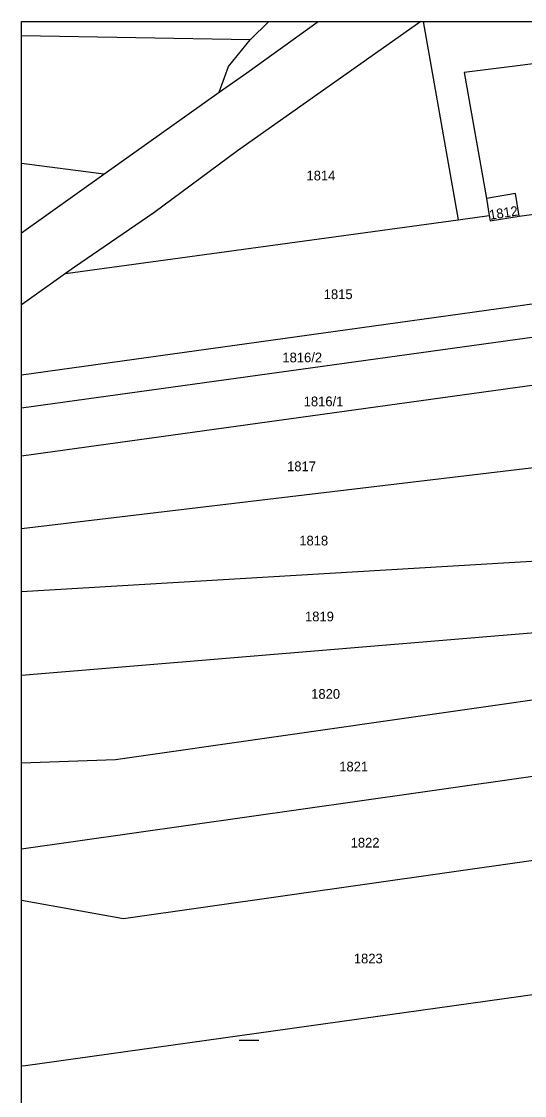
# Model space of a CAD drawing. Extents: x -601800 to -601487, y -1201912 to -1200862.
# Drawn here: x -601783.7 to -601680, y -1201083.7 to -1200862.4 of the extents above; entities that cross this region are included whole.
import ezdxf

# ---------------------------------------------------------------- set-up
doc = ezdxf.new("R2010")
doc.units = 0
for name, color, linetype in [('Hranice parcel', 7, 'Continuous'), ('Parcelní čísla', 7, 'Continuous'), ('x_rám', 7, 'Continuous')]:
    doc.layers.add(name, color=color, linetype=linetype)

msp = doc.modelspace()

# ---------------------------------------------------------------- linework, layer by layer
at = {"layer": 'Hranice parcel'}
for p, q in [((-601700.91, -1200862.35), (-601693.73, -1200903.21)), ((-601766.68, -1200893.84), (-601742.92, -1200876.94)), ((-601766.68, -1200893.84), (-601783.66, -1200891.65)), ((-601681.14, -1200902.44), (-601637.83, -1200896.61)), ((-601687.91, -1200898.84), (-601687.31, -1200902.33)), ((-601774.62, -1200914.32), (-601693.73, -1200903.21)), ((-601693.73, -1200903.21), (-601687.31, -1200902.33)), ((-601783.66, -1200935.2), (-601635.81, -1200914.55)), ((-601634.83, -1200921.38), (-601783.66, -1200942.03)), ((-601632.72, -1200931.05), (-601783.66, -1200951.91))]:
    msp.add_line(p, q, dxfattribs=at)
for points in [[(-601701.43, -1200862.35), (-601739.14, -1200889.01), (-601756.37, -1200901.78), (-601772.74, -1200912.98), (-601774.62, -1200914.32)], [(-601742.92, -1200876.94), (-601737.26, -1200872.91), (-601722.57, -1200862.35)], [(-601732.74, -1200862.35), (-601736.53, -1200866.13)], [(-601736.53, -1200866.13), (-601783.66, -1200865.32)], [(-601742.92, -1200876.94), (-601741, -1200871.62), (-601736.53, -1200866.13)], [(-601642.63, -1200866.63), (-601692.48, -1200872.84), (-601687.91, -1200898.84)], [(-601783.66, -1200905.93), (-601766.68, -1200893.84)], [(-601681.14, -1200902.44), (-601681.93, -1200897.82), (-601687.91, -1200898.84)], [(-601687.31, -1200902.33), (-601687.12, -1200903.46), (-601681.14, -1200902.44)], [(-601774.62, -1200914.32), (-601783.45, -1200920.59), (-601783.66, -1200920.76)], [(-601783.66, -1200966.83), (-601675.86, -1200953.98), (-601626.75, -1200947.04)], [(-601783.66, -1200979.83), (-601676.3, -1200973.45), (-601617.41, -1200963.63)], [(-601783.66, -1200997.03), (-601673.71, -1200987.92), (-601608.55, -1200976.64)], [(-601783.66, -1201015.11), (-601764.33, -1201014.41), (-601598.35, -1200990.64)], [(-601783.66, -1201032.85), (-601702.41, -1201021.28), (-601588.26, -1201005.03)], [(-601783.66, -1201043.44), (-601762.66, -1201047.22), (-601579.23, -1201021.11)], [(-601783.66, -1201077.55), (-601782.86, -1201077.45), (-601677.38, -1201062.7), (-601571.88, -1201047.94)]]:
    msp.add_lwpolyline(points, dxfattribs=at)
at = {"layer": 'x_rám'}
msp.add_line((-601734.8, -1201072.35), (-601738.84, -1201072.35), dxfattribs=at)
msp.add_lwpolyline([(-601486.66, -1200862.35), (-601486.66, -1201912.35), (-601783.66, -1201912.35), (-601783.66, -1200862.35)], close=True, dxfattribs=at)

# ---------------------------------------------------------------- texts
at = {"layer": 'Parcelní čísla'}
for s, p in [('1814', (-601724.96, -1200895.1)), ('1815', (-601721.4, -1200919.56)), ('1816/2', (-601729.92, -1200932.59)), ('1816/1', (-601725.53, -1200941.64)), ('1817', (-601728.95, -1200955.02)), ('1818', (-601726.44, -1200970.32)), ('1819', (-601725.26, -1200985.96)), ('1820', (-601723.99, -1201001.92)), ('1821', (-601718.21, -1201016.89)), ('1822', (-601715.86, -1201032.57)), ('1823', (-601715.2, -1201056.44))]:
    msp.add_text(s, height=2, dxfattribs=at).set_placement(p)
msp.add_text('1812', height=2, rotation=9, dxfattribs=at).set_placement((-601687.15, -1200903.24))

doc.saveas('drawing.dxf')
